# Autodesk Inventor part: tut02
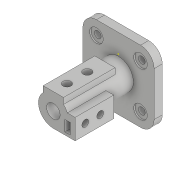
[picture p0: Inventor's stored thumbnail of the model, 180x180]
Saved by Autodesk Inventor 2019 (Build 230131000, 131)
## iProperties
Created: 2015-03
Part Number: tut02
Material: Generic
Document SubType Name: Modeling
Designer: Sandeep
Density: 1 g/cm^3
Appearance: Default
Author: Sandeep
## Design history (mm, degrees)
sketch "Sketch1"
  geometry: L1 (-32.5, -52.5)-(32.5, -52.5); L2 (52.5, -32.5)-(52.5, 32.5); L3 (32.5, 52.5)-(-32.5, 52.5); L4 (-52.5, 32.5)-(-52.5, -32.5); L5 (-52.5, -52.5)-(52.5, 52.5); L6 (52.5, -52.5)-(-52.5, 52.5); A1 r 20 centre (32.5, 32.5) between (52.5, 32.5) and (32.5, 52.5); A2 r 20 centre (32.5, -32.5) between (32.5, -52.5) and (52.5, -32.5); A3 r 20 centre (-32.5, -32.5) between (-52.5, -32.5) and (-32.5, -52.5); A4 r 20 centre (-32.5, 32.5) between (-32.5, 52.5) and (-52.5, 32.5); 1 further point
  constraints: 12 end point, 8 point on circle, 8 point on line, 8 tangent, 4 centre point, 2 equal radius, 2 midpoint, 2 parallel, 1 horizontal, 1 perpendicular
  dimensions: "d0" = 105 distance of L6.start L5.end; "d1" = 105 distance of L5.start L6.start; "d2" = 20 radius of A1; "d3" = 20 radius of A2
extrude "Extrusion1" new body sketch "Sketch1" distance "d4" = 12; taper "d5" = 0 deg
hole "Hole1" diameter "d8" = 10; stored, may be unused: countersink angle "d12" = 90 deg, drill point angle "d14" = 118 deg; dims "d9" = 6, "d10" = 20, "d11" = 2, "d13" = 8, "d15" = 10, "d16" = 10
hole "Hole2" diameter "d19" = 10; stored, may be unused: countersink angle "d23" = 90 deg, drill point angle "d25" = 118 deg; dims "d17" = 10, "d18" = 10, "d20" = 6, "d21" = 20, "d22" = 2, "d24" = 8
hole "Hole3" diameter "d28" = 10; stored, may be unused: countersink angle "d32" = 90 deg, drill point angle "d34" = 118 deg; dims "d26" = 10, "d27" = 10, "d29" = 6, "d30" = 20, "d31" = 2, "d33" = 8
hole "Hole4" diameter "d37" = 10; stored, may be unused: countersink angle "d41" = 90 deg, drill point angle "d43" = 118 deg; dims "d35" = 10, "d36" = 10, "d38" = 6, "d39" = 20, "d40" = 2, "d42" = 8
sketch "Sketch2"
  geometry: C1 r 22 at (0, 0); 1 further point
  constraints: 1 centre point, 1 coincident
  dimensions: "d44" = 44 diameter of C1
extrude "Extrusion2" join sketch "Sketch2" distance "d45" = 96; taper "d46" = 0 deg
sketch "Sketch3"
  geometry: L1 (-15, 16.093)-(-15, 25); L2 (15, 16.093)-(15, 25); L3 (-15, 25)-(15, 25); L4 (0, 0)-(20.619, 0); L5 (0, 6.043)-(0, 0); A1 r 22 centre (0, 0) between (15, 16.093) and (-15, 16.093); 1 further point
  constraints: 10 end point, 3 vertical, 2 horizontal, 2 point on circle, 1 centre point, 4 other
  dimensions: "d48" = 25 distance from line of point (0, 0) L3; "d49" = 30 distance of L1.end L2.end
extrude "Extrusion3" join sketch "Sketch3" distance "d51" = 76; taper "d52" = 0 deg
sketch "Sketch4"
  geometry: L1 (20.494, 8)-(32, 8); L2 (32, 8)-(32, -22); L3 (0, 0)-(37.067, 0); L4 (0, -22)-(32, -22); A1 r 22 centre (0, 0) between (20.494, 8) and (0, -22) reference; A2 r 22 centre (0, 0) between (0, -22) and (20.494, 8); 1 further point
  constraints: 8 end point, 5 point on circle, 2 horizontal, 2 perpendicular, 1 centre point, 1 concentric, 1 tangent
  dimensions: "d53" = 30 distance of L2.end L1.end; "d54" = 32 distance from line of L2 point (0, 0)
extrude "Extrusion4" join sketch "Sketch4" distance "d55" = 57; taper "d56" = 0 deg
sketch "Sketch5"
  geometry: L1 (17, -2)-(25, -2); L2 (25, -2)-(25, -18); L3 (25, -18)-(17, -18); L4 (17, -18)-(17, -2); 1 further point
  constraints: 8 end point, 2 parallel, 1 horizontal, 1 perpendicular
  dimensions: "d57" = 16 distance of L1.end L2.end; "d58" = 2 distance from line of point (0, 0) L1; "d59" = 25 distance from line of point (0, 0) L2; "d60" = 8 distance of L2.end L3.end
extrude "Extrusion5" cut sketch "Sketch5" distance "d61" = 50; taper "d62" = 0 deg
sketch "Sketch6"
  geometry: 1 further point
sketch "Sketch8"
  geometry: 1 further point
hole "Hole6" diameter "d77" = 20; stored, may be unused: countersink angle "d81" = 90 deg, drill point angle "d83" = 118 deg; dims "d75" = 10, "d76" = 10, "d78" = 6, "d79" = 4, "d80" = 2, "d82" = 96
hole "Hole7" diameter "d86" = 12; stored, may be unused: countersink angle "d90" = 90 deg, drill point angle "d92" = 118 deg; dims "d84" = 20, "d85" = 15, "d87" = 6, "d88" = 4, "d89" = 2, "d91" = 96
hole "Hole8" diameter "d95" = 12; stored, may be unused: countersink angle "d99" = 90 deg, drill point angle "d101" = 118 deg; dims "d93" = 50, "d94" = 15, "d96" = 6, "d97" = 4, "d98" = 2, "d100" = 96
hole "Hole10" diameter "d113" = 10; stored, may be unused: countersink angle "d117" = 90 deg, drill point angle "d119" = 118 deg; dims "d111" = 15, "d112" = 15, "d114" = 6, "d115" = 4, "d116" = 2, "d118" = 96
hole "Hole11" diameter "d122" = 10; stored, may be unused: countersink angle "d126" = 90 deg, drill point angle "d128" = 118 deg; dims "d120" = 37, "d121" = 15, "d123" = 6, "d124" = 4, "d125" = 2, "d127" = 96
body "Solid1"
